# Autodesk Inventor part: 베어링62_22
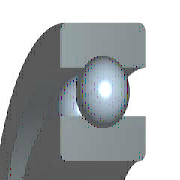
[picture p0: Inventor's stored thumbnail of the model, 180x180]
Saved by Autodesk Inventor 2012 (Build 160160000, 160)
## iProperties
Created: 2009-02
Part Number: 베어링62_22
Material: 강, 연강
Description: 깊은 그루브 볼 베어링
Document SubType Name: Modeling
Standard: KS B 2023
Designer: KYOUNG IL JANG
Standards Organization: KS
Language: ko-KR
Size Designation: 62/22 - 22 x 50 x 14
Categories: <MemberInstance><Categories><Category DisplayName="샤프트 부품" InternalName="7f7aeb1f-a693-4053-b835-cee3144e0d98" Mnemonic="SHFT"><Category DisplayName="베어링" Inter
Density: 1 g/cm^3
IsCustomPart: 0
Author: KYOUNG IL JANG
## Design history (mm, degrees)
revolve "본체" stored, may be unused: angle "d6" = 90 deg
revolve "볼" stored, may be unused: angle "d7" = 90 deg
pattern_circular "IDS_ARRAYBALL[SIMPL:T]" dims angle "d3" = 360 deg
body "Solid1"
sketch "스케치" dims "d0" = 7.28 (= -0.26 x WD + 0.26 x BD)
  geometry: L1 (3.36, 18)-(10.64, 18); L2 (7, 18)-(7, 14.36); L3 (7, 18)-(7, 21.64); L4 (4.295, 15.564)-(0, 15.564); L5 (0, 11)-(14, 11); L6 (4.295, 20.436)-(0, 20.436); L7 (0, 25)-(14, 25); L8 (14, 11)-(14, 15.564); L9 (9.705, 15.564)-(14, 15.564); L10 (9.705, 20.436)-(14, 20.436); L11 (14, 25)-(14, 20.436); L12 (-1.4, 0)-(8.4, 0) reference; L13 (0, -0.3)-(0, 5.3) reference
  constraints: 22 end point, 4 point on line, 2 collinear, 2 perpendicular, 2 symmetric about line, 1 midpoint, 1 parallel, 14 other
  dimensions: "d9" = 22 diameter of L5 L12 (= WD); "d11" = 50 diameter of L7 L12 (= BD); "d12" = 14 distance between parallel lines of L8 L13 (= KB); "d13" = 31.128 diameter of L9 L12 (= 0.326 x BD + 0.674 x WD)
fillet "모깎기1" dims "d1" = 1 (= KRS)
other parameters: "WD" = 22 [user parameter; used in 5 equation terms], "BD" = 50 [user parameter; used in 5 equation terms], "KB" = 14 [user parameter; used in 1 equation term], "KRS" = 1 [user parameter; used in 1 equation term], "d4" = 0, "d5" = 0, "d8" = 0, "d14" = 0, "d15" = 0, "BBA" = 0 [user parameter], "BC0" = 7154000 [user parameter], "BC" = 1.2233e+07 [user parameter], "BR" = 25 (= 0.5 x BD) [user parameter], "WR" = 11 (= 0.5 x WD) [user parameter]
